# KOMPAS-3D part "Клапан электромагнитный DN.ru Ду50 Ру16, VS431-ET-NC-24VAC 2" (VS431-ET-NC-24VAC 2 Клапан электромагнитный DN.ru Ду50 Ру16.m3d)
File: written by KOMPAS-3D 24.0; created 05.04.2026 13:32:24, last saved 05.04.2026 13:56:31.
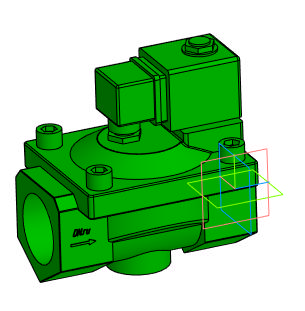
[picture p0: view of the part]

Document properties: Автор: artio; Полное имя файла: C:\Users\artio\OneDrive\Рабочий стол\Клапан электромагнитный DN.ru\VS431\VS431-ET-NC\VS431-ET-NC-24VAC\Ду50\VS431-ET-NC-24VAC 2 Клапан электромагнитный DN.ru Ду50 Ру16.m3d

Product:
- Body: Тело 1  | qty 1
    Масса: 6.703651
- Part/product: Клапан электромагнитный DN.ru Ду50 Ру16  | designation VS431-ET-NC-24VAC 2
    Масса: 3.341
    Раздел спецификации: Прочие изделия
    Примечание: D130-05507
    additional columns: ef56311e-7521-43dc-8291-0e6108b3d81d; artio; c; Шероховатость не задана; Да

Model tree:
1. Операция без истории:1

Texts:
  VS431-ET-NC-24VAC 2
